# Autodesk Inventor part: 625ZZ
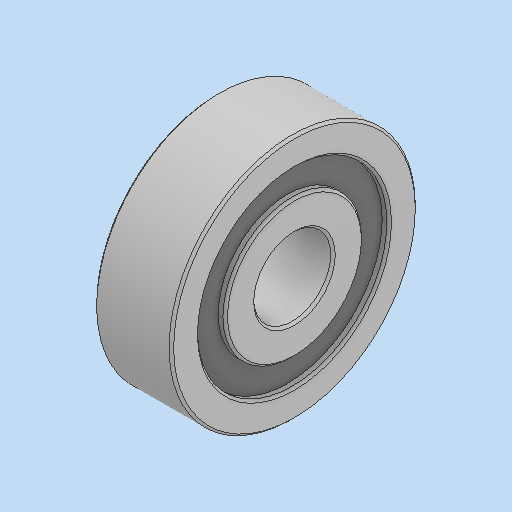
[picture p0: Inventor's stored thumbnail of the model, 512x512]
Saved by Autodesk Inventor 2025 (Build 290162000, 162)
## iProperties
Created: 2025-05
Part Number: 625ZZ
Material: Generico
Description: 625ZZ
Document SubType Name: Modeling
Designer: R5800u
Density: 1 g/cm^3
Appearance: Default
Author: R5800u
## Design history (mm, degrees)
feature "625ZZ"
node "Solido1"
